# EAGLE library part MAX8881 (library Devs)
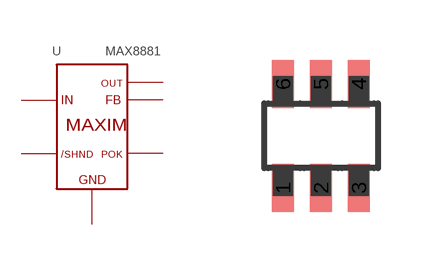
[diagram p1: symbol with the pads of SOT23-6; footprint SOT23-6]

Designator prefix -

## MAX8881  [SOT23-6]
1  P$IN  in
2  P$GND  pwr
3  P$OUT  out
4  P$FB  out
5  P$/SHND  in
6  P$POK  out

## Footprint SOT23-6 (pad centres in mm)
smd 0.55 x 1.2: 1 -0.95,-1.3; 2 0,-1.3; 3 0.95,-1.3; 4 0.95,1.3; 5 0,1.3; 6 -0.95,1.3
